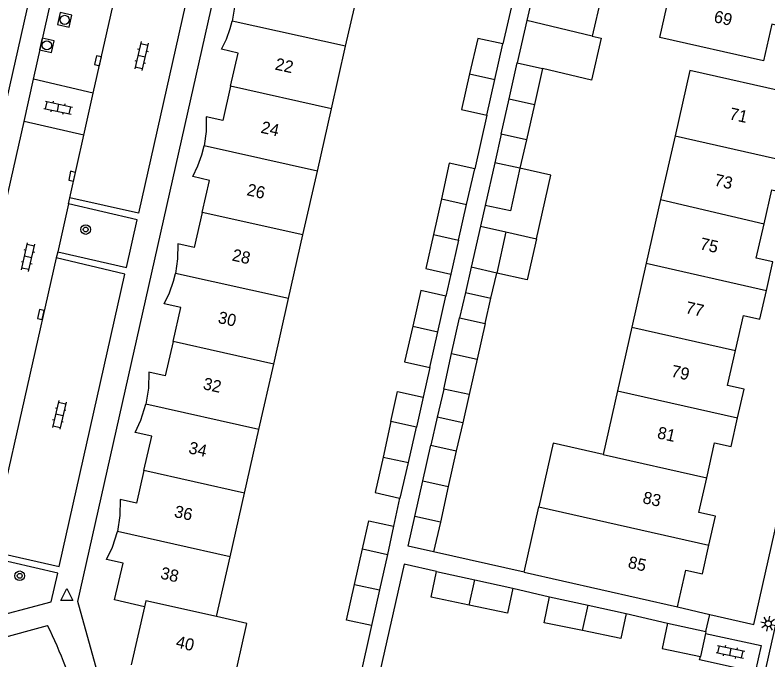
# Model space of a CAD drawing. Extents: x 128000 to 131008, y 398996 to 402500.
# Drawn here: x 128856.3 to 128918.6, y 399181.9 to 399235.3 of the extents above; entities that cross this region are included whole.
import ezdxf

# ---------------------------------------------------------------- set-up
doc = ezdxf.new("R2010")
doc.units = 0
for name, color, linetype in [('gg-afsc-erfafscheiding', 7, 'Continuous'), ('gg-anno-huisnummerreeks BGT', 7, 'Continuous'), ('gg-bbg-bijgebouw', 7, 'Continuous'), ('gg-bbg-gedigitaliseerde bebouwing', 7, 'Continuous'), ('gg-bbg-gedigitaliseerde bijgebouw', 7, 'Continuous'), ('gg-bbg-hoofdgebouw', 7, 'Continuous'), ('gg-bbg-luifel en loopbrug', 7, 'Continuous'), ('gg-bbg-tussenscheiding', 7, 'Continuous'), ('gg-knt-verharding', 7, 'Continuous'), ('gg-knt-verharding nz', 7, 'Continuous'), ('gt-grn-weggrens', 7, 'Continuous'), ('gt-symb-boom', 7, 'Continuous'), ('gt-symb-klinker verharding', 7, 'Continuous'), ('gt-symb-kolk', 7, 'Continuous'), ('gt-symb-lichtmast', 7, 'Continuous'), ('gt-symb-rioolschacht', 7, 'Continuous'), ('gt-symb-waterafsluiter', 7, 'Continuous')]:
    doc.layers.add(name, color=color, linetype=linetype)

# ---------------------------------------------------------------- blocks, each defined once
blk = doc.blocks.new('gt0-KL1')
at = {"layer": 'gt-symb-klinker verharding'}
for p, q in [((-1.15, 0.3), (1.15, 0.3)), ((-1, -0.3), (-1, 0.3)), ((-0.5, 0.3), (-0.5, 0.45)), ((0, -0.3), (0, 0.3)), ((0.5, 0.3), (0.5, 0.45)), ((1, -0.3), (1, 0.3)), ((-1.15, -0.3), (1.15, -0.3)), ((-0.5, -0.45), (-0.5, -0.3)), ((0.5, -0.45), (0.5, -0.3))]:
    blk.add_line(p, q, dxfattribs=at)
blk = doc.blocks.new('gt0-BOOM')
at = {"layer": 'gt-symb-boom'}
for radius in [0.4, 0.2]:
    blk.add_circle((0, 0), radius, dxfattribs=at)
blk = doc.blocks.new('gt0-WAFSL')
at = {"layer": 'gt-symb-waterafsluiter'}
for p, q in [((-0.5, -0.333), (0, 0.667)), ((0, 0.667), (0.5, -0.333)), ((0.5, -0.333), (-0.5, -0.333))]:
    blk.add_line(p, q, dxfattribs=at)
blk = doc.blocks.new('gt0-KOLK')
at = {"layer": 'gt-symb-kolk'}
blk.add_lwpolyline([(0, 0), (0.375, 0), (0.375, 0.4), (-0.375, 0.4), (-0.375, 0), (0, 0)], dxfattribs=at)
blk = doc.blocks.new('gt0-RS')
at = {"layer": 'gt-symb-rioolschacht'}
blk.add_lwpolyline([(-0.5, -0.5), (0.5, -0.5), (0.5, 0.5), (-0.5, 0.5)], close=True, dxfattribs=at)
blk.add_circle((0, 0), 0.375, dxfattribs=at)
blk = doc.blocks.new('gt0-LMAST')
at = {"layer": 'gt-symb-lichtmast'}
for p, q in [((-0.182, 0.173), (-0.447, 0.438)), ((-0.005, 0.246), (-0.005, 0.621)), ((0.172, 0.173), (0.437, 0.438)), ((-0.255, -0.004), (-0.63, -0.004)), ((-0.182, -0.181), (-0.447, -0.446)), ((-0.005, -0.254), (-0.005, -0.629)), ((0.437, -0.446), (0.172, -0.181)), ((0.245, -0.004), (0.62, -0.004))]:
    blk.add_line(p, q, dxfattribs=at)
blk.add_circle((-0.005, -0.004), 0.25, dxfattribs=at)

msp = doc.modelspace()

# ---------------------------------------------------------------- linework, layer by layer
at = {"layer": 'gg-afsc-erfafscheiding'}
for p, q in [((128897.751, 399237.532), (128896.704, 399232.891)), ((128895.372, 399226.992), (128894.369, 399222.546)), ((128892.404, 399213.839), (128891.99, 399212.005)), ((128890.659, 399206.106), (128890.103, 399203.644)), ((128888.149, 399195.298), (128887.659, 399192.97)), ((128898.458, 399189.154), (128890.966, 399190.844)), ((128897.537, 399187.856), (128900.566, 399187.118)), ((128911.16, 399186.291), (128913.82, 399185.67)), ((128906.903, 399185.745), (128910.31, 399184.95)), ((128885.837, 399184.742), (128884.858, 399180.403)), ((128912.974, 399181.898), (128913.04, 399182.191))]:
    msp.add_line(p, q, dxfattribs=at)
msp.add_lwpolyline([(128891.2, 399189.229), (128888.522, 399189.833), (128885.467, 399176.29), (128886.4, 399176.08)], dxfattribs=at)
at = {"layer": 'gg-bbg-bijgebouw'}
for p, q in [((128896.038, 399229.942), (128896.704, 399232.891)), ((128895.372, 399226.992), (128896.038, 399229.942)), ((128893.705, 399219.601), (128894.369, 399222.546)), ((128891.611, 399220.068), (128890.954, 399217.121)), ((128893.04, 399216.656), (128893.705, 399219.601)), ((128890.954, 399217.121), (128893.04, 399216.656)), ((128891.325, 399209.056), (128891.99, 399212.005)), ((128890.659, 399206.106), (128891.325, 399209.056)), ((128887.446, 399201.651), (128886.788, 399198.7)), ((128889.547, 399201.182), (128887.446, 399201.651)), ((128888.882, 399198.233), (128889.547, 399201.182)), ((128884.425, 399188.155), (128885.083, 399191.106)), ((128885.083, 399191.106), (128887.169, 399190.641)), ((128887.169, 399190.641), (128886.503, 399187.692)), ((128886.503, 399187.692), (128885.837, 399184.742)), ((128910.31, 399184.95), (128913.49, 399184.261)), ((128913.455, 399184.101), (128913.04, 399182.191)), ((128913.49, 399184.261), (128913.455, 399184.101))]:
    msp.add_line(p, q, dxfattribs=at)
for points in [[(128896.704, 399232.891), (128894.618, 399233.356), (128893.952, 399230.407)], [(128893.952, 399230.407), (128893.286, 399227.457), (128895.372, 399226.992)], [(128894.369, 399222.546), (128892.268, 399223.014), (128891.611, 399220.068)], [(128891.99, 399212.005), (128889.904, 399212.47), (128889.239, 399209.521)], [(128889.239, 399209.521), (128888.573, 399206.571), (128890.659, 399206.106)], [(128886.788, 399198.7), (128886.13, 399195.748), (128888.149, 399195.298)], [(128888.149, 399195.298), (128888.216, 399195.283), (128888.882, 399198.233)], [(128885.837, 399184.742), (128883.767, 399185.203), (128884.425, 399188.155)], [(128910.31, 399184.95), (128909.88, 399182.85), (128913.04, 399182.191)]]:
    msp.add_lwpolyline(points, dxfattribs=at)
at = {"layer": 'gg-bbg-gedigitaliseerde bebouwing'}
for p, q in [((128912.165, 399230.691), (128910.943, 399225.277)), ((128910.943, 399225.277), (128909.753, 399220.004)), ((128909.753, 399220.004), (128908.563, 399214.732)), ((128908.563, 399214.732), (128907.373, 399209.459)), ((128907.373, 399209.459), (128906.183, 399204.187)), ((128906.183, 399204.187), (128904.993, 399198.915)), ((128898.458, 399189.154), (128899.674, 399194.568)), ((128898.458, 399189.154), (128911.16, 399186.291))]:
    msp.add_line(p, q, dxfattribs=at)
msp.add_lwpolyline([(128904.993, 399198.915), (128900.866, 399199.847), (128899.674, 399194.568)], dxfattribs=at)
at = {"layer": 'gg-bbg-gedigitaliseerde bijgebouw'}
for p, q in [((128897.216, 399228.338), (128897.882, 399231.323)), ((128897.882, 399231.323), (128899.983, 399230.855)), ((128899.983, 399230.855), (128899.317, 399227.869)), ((128896.566, 399225.42), (128897.216, 399228.338)), ((128899.317, 399227.869), (128898.667, 399224.952)), ((128898.667, 399224.952), (128896.566, 399225.42)), ((128896.036, 399223.059), (128895.239, 399219.529)), ((128898.113, 399222.596), (128896.036, 399223.059)), ((128898.113, 399222.596), (128897.336, 399219.067)), ((128897.336, 399219.067), (128895.239, 399219.529)), ((128894.848, 399217.795), (128894.084, 399214.407)), ((128894.848, 399217.795), (128896.953, 399217.325)), ((128896.953, 399217.325), (128896.205, 399213.93)), ((128896.205, 399213.93), (128894.084, 399214.407)), ((128892.463, 399207.265), (128893.124, 399210.232)), ((128893.124, 399210.232), (128895.226, 399209.764)), ((128895.226, 399209.764), (128894.563, 399206.794)), ((128891.808, 399204.329), (128892.463, 399207.265)), ((128894.563, 399206.794), (128893.91, 399203.861)), ((128893.91, 399203.861), (128891.808, 399204.329)), ((128890.087, 399196.734), (128890.745, 399199.685)), ((128890.745, 399199.685), (128892.847, 399199.217)), ((128892.847, 399199.217), (128892.187, 399196.258)), ((128889.429, 399193.782), (128890.087, 399196.734)), ((128892.187, 399196.258), (128891.531, 399193.314)), ((128891.531, 399193.314), (128889.429, 399193.782)), ((128891.2, 399189.229), (128894.381, 399188.54)), ((128894.381, 399188.54), (128897.537, 399187.856)), ((128900.566, 399187.118), (128903.764, 399186.425)), ((128903.764, 399186.425), (128906.903, 399185.745))]:
    msp.add_line(p, q, dxfattribs=at)
for points in [[(128893.925, 399186.44), (128890.763, 399187.093), (128891.2, 399189.229)], [(128897.537, 399187.856), (128897.087, 399185.786), (128893.925, 399186.44)], [(128903.291, 399184.328), (128900.129, 399184.982), (128900.566, 399187.118)], [(128906.903, 399185.745), (128906.453, 399183.675), (128903.291, 399184.328)]]:
    msp.add_lwpolyline(points, dxfattribs=at)
at = {"layer": 'gg-bbg-hoofdgebouw'}
for p, q in [((128883.69, 399232.694), (128884.881, 399237.964)), ((128882.522, 399227.522), (128883.69, 399232.694)), ((128881.354, 399222.354), (128882.522, 399227.522)), ((128880.162, 399217.084), (128881.354, 399222.354)), ((128878.971, 399211.81), (128880.162, 399217.084)), ((128877.748, 399206.398), (128878.971, 399211.81)), ((128876.525, 399200.987), (128877.748, 399206.398)), ((128875.334, 399195.717), (128876.525, 399200.987)), ((128874.144, 399190.447), (128875.334, 399195.717)), ((128873.023, 399185.49), (128874.144, 399190.447)), ((128867.05, 399186.3), (128865.938, 399181.492))]:
    msp.add_line(p, q, dxfattribs=at)
for points in [[(128876.522, 399239.828), (128875.91, 399237.11), (128874.549, 399237.419), (128874.524, 399236.093), (128874.314, 399234.784)], [(128920.85, 399236.594), (128920.31, 399234.211), (128918.95, 399234.521), (128918.26, 399231.49), (128909.69, 399233.421), (128910.911, 399238.835)], [(128874.172, 399229.383), (128874.79, 399232.14), (128873.43, 399232.45), (128873.832, 399233.293), (128874.149, 399234.171), (128874.314, 399234.784)], [(128921.45, 399225.57), (128920.09, 399225.88), (128920.74, 399228.76), (128912.165, 399230.691)], [(128874.172, 399229.383), (128873.54, 399226.56), (128872.169, 399226.869), (128872.152, 399225.65), (128871.978, 399224.444)], [(128871.823, 399218.944), (128872.42, 399221.6), (128871.05, 399221.91), (128871.468, 399222.792), (128871.793, 399223.712), (128871.978, 399224.444)], [(128918.309, 399217.991), (128918.95, 399220.82), (128920.31, 399220.511)], [(128871.823, 399218.944), (128871.17, 399216.04), (128869.799, 399216.339), (128869.788, 399215.111), (128869.614, 399213.895)], [(128918.504, 399212.479), (128919.04, 399214.86), (128917.67, 399215.171), (128918.309, 399217.991)], [(128869.413, 399208.256), (128870.05, 399211.07), (128868.68, 399211.37), (128869.118, 399212.288), (128869.453, 399213.249), (128869.614, 399213.895)], [(128915.945, 399207.521), (128916.6, 399210.411), (128917.97, 399210.11), (128918.504, 399212.479)], [(128869.413, 399208.256), (128868.77, 399205.411), (128867.409, 399205.719), (128867.383, 399204.388), (128867.172, 399203.073)], [(128916.125, 399201.943), (128916.66, 399204.32), (128915.29, 399204.63), (128915.945, 399207.521)], [(128867.007, 399197.574), (128867.65, 399200.431), (128866.29, 399200.74), (128866.755, 399201.741), (128867.172, 399203.073)], [(128913.569, 399196.982), (128914.22, 399199.87), (128915.59, 399199.57), (128916.125, 399201.943)], [(128867.007, 399197.574), (128866.4, 399194.88), (128865.039, 399195.179), (128865.019, 399193.845), (128864.807, 399192.528)], [(128913.744, 399191.408), (128914.28, 399193.791), (128912.92, 399194.1), (128913.569, 399196.982)], [(128867.05, 399186.3), (128864.58, 399186.87), (128865.29, 399189.921), (128863.92, 399190.22), (128864.404, 399191.248), (128864.807, 399192.528)], [(128911.16, 399186.291), (128911.84, 399189.34), (128913.21, 399189.031), (128913.744, 399191.408)], [(128874.321, 399179.623), (128875.52, 399184.925), (128873.023, 399185.49)]]:
    msp.add_lwpolyline(points, dxfattribs=at)
at = {"layer": 'gg-bbg-luifel en loopbrug'}
for p, q in [((128905.578, 399240.019), (128904.096, 399233.546)), ((128899.474, 399238.315), (128898.678, 399234.819)), ((128898.678, 399234.819), (128897.882, 399231.323)), ((128904.096, 399233.546), (128898.678, 399234.819)), ((128896.566, 399225.42), (128896.036, 399223.059)), ((128898.667, 399224.952), (128898.113, 399222.596)), ((128895.239, 399219.529), (128894.848, 399217.795)), ((128896.953, 399217.325), (128899.487, 399216.759)), ((128893.04, 399216.656), (128892.404, 399213.839)), ((128894.084, 399214.407), (128893.604, 399212.32)), ((128895.715, 399211.847), (128896.205, 399213.93)), ((128893.604, 399212.32), (128893.124, 399210.232)), ((128893.604, 399212.32), (128895.715, 399211.847)), ((128895.226, 399209.764), (128895.715, 399211.847)), ((128891.808, 399204.329), (128891.277, 399202.007)), ((128890.103, 399203.644), (128889.547, 399201.182)), ((128893.91, 399203.861), (128893.379, 399201.539)), ((128891.277, 399202.007), (128890.745, 399199.685)), ((128893.379, 399201.539), (128891.277, 399202.007)), ((128893.379, 399201.539), (128892.847, 399199.217)), ((128887.659, 399192.97), (128887.169, 399190.641)), ((128891.531, 399193.314), (128890.966, 399190.844))]:
    msp.add_line(p, q, dxfattribs=at)
for points in [[(128904.096, 399233.546), (128904.84, 399233.371), (128904.026, 399229.905), (128899.983, 399230.855)], [(128899.487, 399216.759), (128900.671, 399222.027), (128898.113, 399222.596)], [(128890.954, 399217.121), (128890.326, 399214.302), (128892.404, 399213.839)], [(128899.487, 399216.759), (128898.724, 399213.363), (128896.205, 399213.93)], [(128887.446, 399201.651), (128887.995, 399204.114), (128890.103, 399203.644)], [(128885.083, 399191.106), (128885.601, 399193.428), (128887.659, 399192.97)], [(128890.966, 399190.844), (128888.866, 399191.317), (128889.429, 399193.782)]]:
    msp.add_lwpolyline(points, dxfattribs=at)
at = {"layer": 'gg-bbg-tussenscheiding'}
for p, q in [((128883.69, 399232.694), (128874.314, 399234.784)), ((128893.952, 399230.407), (128896.038, 399229.942)), ((128882.522, 399227.522), (128874.172, 399229.383)), ((128897.216, 399228.338), (128899.317, 399227.869)), ((128910.943, 399225.277), (128920.88, 399223.042)), ((128881.354, 399222.354), (128871.978, 399224.444)), ((128891.611, 399220.068), (128893.705, 399219.601)), ((128909.753, 399220.004), (128918.309, 399217.991)), ((128880.162, 399217.084), (128871.823, 399218.944)), ((128908.563, 399214.732), (128918.504, 399212.479)), ((128878.971, 399211.81), (128869.614, 399213.895)), ((128889.239, 399209.521), (128891.325, 399209.056)), ((128907.373, 399209.459), (128915.945, 399207.521)), ((128877.748, 399206.398), (128869.413, 399208.256)), ((128892.463, 399207.265), (128894.563, 399206.794)), ((128906.183, 399204.187), (128916.125, 399201.943)), ((128876.525, 399200.987), (128867.172, 399203.073)), ((128886.788, 399198.7), (128888.882, 399198.233)), ((128904.993, 399198.915), (128913.569, 399196.982)), ((128875.334, 399195.717), (128867.007, 399197.574)), ((128890.087, 399196.734), (128892.187, 399196.258)), ((128899.674, 399194.568), (128913.744, 399191.408)), ((128874.144, 399190.447), (128864.807, 399192.528)), ((128893.925, 399186.44), (128894.381, 399188.54)), ((128884.425, 399188.155), (128886.503, 399187.692)), ((128903.291, 399184.328), (128903.764, 399186.425))]:
    msp.add_line(p, q, dxfattribs=at)
msp.add_lwpolyline([(128873.023, 399185.49), (128867.161, 399186.797), (128867.05, 399186.3)], dxfattribs=at)
at = {"layer": 'gg-knt-verharding'}
for p, q in [((128862.799, 399228.807), (128857.873, 399229.977)), ((128862.025, 399225.331), (128857.085, 399226.473)), ((128927.598, 399222.072), (128914.483, 399163.569)), ((128860.768, 399219.65), (128860.867, 399220.158)), ((128860.768, 399219.65), (128859.88, 399215.67)), ((128859.88, 399215.67), (128859.756, 399215.193)), ((128854.126, 399183.404), (128859.042, 399184.744))]:
    msp.add_line(p, q, dxfattribs=at)
for points in [[(128864.601, 399175.707), (128861.54, 399186.741), (128885.35, 399292.58)], [(128867.508, 399272.586), (128865.697, 399273.046), (128848.658, 399197.395), (128850.441, 399196.968)], [(128865.796, 399241.942), (128871.439, 399240.631), (128866.551, 399218.876), (128860.867, 399220.158)], [(128859.88, 399215.67), (128865.566, 399214.389), (128866.459, 399218.333), (128860.768, 399219.65)], [(128913.82, 399185.67), (128917.46, 399184.84), (128925.25, 399219.398)], [(128854.26, 399190.927), (128859.997, 399189.624), (128865.425, 399213.846), (128859.756, 399215.193)], [(128853.695, 399185.214), (128859.332, 399186.725), (128859.894, 399189.096), (128854.137, 399190.413)], [(128913.455, 399184.101), (128918.063, 399183.087), (128917.566, 399180.901), (128912.974, 399181.898)]]:
    msp.add_lwpolyline(points, dxfattribs=at)
msp.add_arc((128811.408, 399161.823), 52.862, 17.67317, 25.69662, dxfattribs=at)
at = {"layer": 'gg-knt-verharding nz'}
for p, q in [((128862.799, 399228.807), (128865.796, 399241.942)), ((128857.873, 399229.977), (128859.937, 399239.143)), ((128857.085, 399226.473), (128857.873, 399229.977)), ((128862.025, 399225.331), (128862.799, 399228.807)), ((128854.288, 399214.056), (128857.085, 399226.473)), ((128860.867, 399220.158), (128862.025, 399225.331)), ((128859.756, 399215.193), (128854.93, 399193.884))]:
    msp.add_line(p, q, dxfattribs=at)
at = {"layer": 'gt-grn-weggrens'}
msp.add_line((128913.49, 399184.261), (128913.82, 399185.67), dxfattribs=at)

# ---------------------------------------------------------------- block references
at = {"layer": 'gt-symb-boom'}
for p in [(128862.191, 399217.529), (128856.733, 399188.866)]:
    msp.add_blockref('gt0-BOOM', p, dxfattribs=at)
at = {"layer": 'gt-symb-klinker verharding'}
for p, rotation in [((128866.803, 399231.893), -103.11914463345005), ((128859.914, 399227.611), -12.006708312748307), ((128857.422, 399215.252), 77.29726808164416), ((128860.007, 399202.194), -103.11914463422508), ((128915.534, 399182.574), -11.534620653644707)]:
    msp.add_blockref('gt0-KL1', p, dxfattribs=dict(at, rotation=rotation))
at = {"layer": 'gt-symb-kolk'}
for p, rotation in [((128863.402, 399231.456), 77.17287657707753), ((128861.252, 399221.894), 77.46497665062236), ((128858.684, 399210.449), 77.28466301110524)]:
    msp.add_blockref('gt0-KOLK', p, dxfattribs=dict(at, rotation=rotation))
at = {"layer": 'gt-symb-lichtmast', "rotation": 77.28466301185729}
msp.add_blockref('gt0-LMAST', (128918.651, 399184.908), dxfattribs=at)
at = {"layer": 'gt-symb-rioolschacht', "rotation": 77.29726808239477}
for p in [(128860.455, 399234.886), (128858.974, 399232.772)]:
    msp.add_blockref('gt0-RS', p, dxfattribs=at)
at = {"layer": 'gt-symb-waterafsluiter'}
msp.add_blockref('gt0-WAFSL', (128860.629, 399187.144), dxfattribs=at)

# ---------------------------------------------------------------- texts
at = {"layer": 'gg-anno-huisnummerreeks BGT'}
for s, rotation, p in [('69', 347.2, (128914.093, 399234.709)), ('22', 347.4, (128877.79, 399230.783)), ('71', 347.3, (128915.371, 399226.669)), ('24', 347.4, (128876.617, 399225.55)), ('73', 347.2, (128914.133, 399221.182)), ('26', 347.3, (128875.451, 399220.382)), ('75', 347.2, (128912.938, 399215.906)), ('28', 347.4, (128874.235, 399214.973)), ('77', 347.2, (128911.75, 399210.626)), ('30', 347.2, (128873.068, 399209.807)), ('79', 347.2, (128910.558, 399205.366)), ('32', 347.3, (128871.83, 399204.328)), ('81', 347.3, (128909.412, 399200.263)), ('34', 347.3, (128870.636, 399199.021)), ('83', 347.3, (128908.203, 399194.898)), ('36', 347.4, (128869.451, 399193.743)), ('85', 347.4, (128906.99, 399189.538)), ('38', 346.9, (128868.304, 399188.651)), ('40', 347, (128869.584, 399182.954))]:
    msp.add_text(s, height=1, rotation=rotation, dxfattribs=at).set_placement(p)

doc.saveas('drawing.dxf')
